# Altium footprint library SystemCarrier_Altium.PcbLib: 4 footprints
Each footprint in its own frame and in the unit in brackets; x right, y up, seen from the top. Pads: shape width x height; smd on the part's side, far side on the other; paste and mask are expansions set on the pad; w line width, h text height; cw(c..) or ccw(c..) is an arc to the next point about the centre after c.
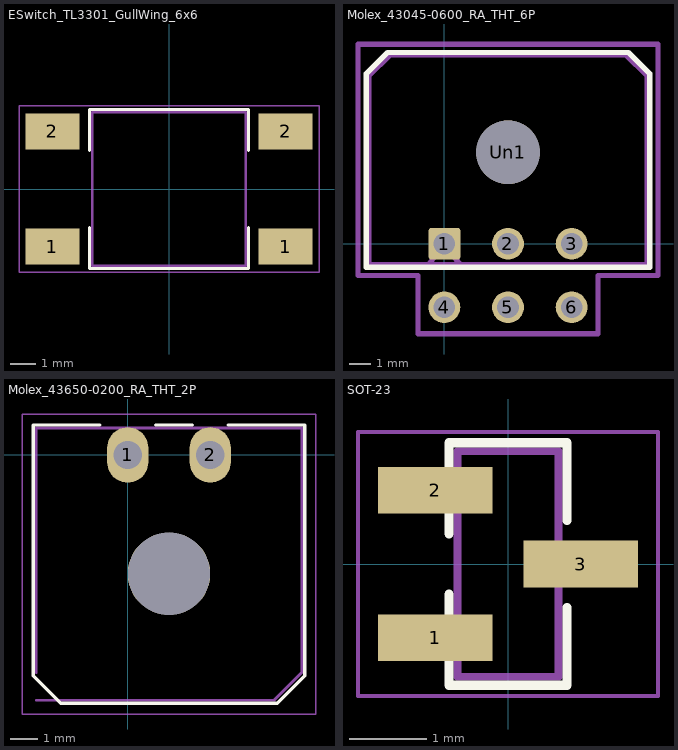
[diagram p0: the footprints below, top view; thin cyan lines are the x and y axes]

## ESwitch_TL3301_GullWing_6x6 [mm] "E-Switch TL3301 series, 6 x 6 mm gull-wing tactile switch"
height 4.3
pads (4):
  rect 2.1x1.4 smd: 1(-4.55,-2.25) 1(4.55,-2.25) 2(-4.55,2.25) 2(4.55,2.25)
F.SilkS:
  lines w0.12: -3.1,-1.5 -3.1,-3.1 3.1,-3.1 3.1,-1.5 ; -3.1,1.5 -3.1,3.1 3.1,3.1 3.1,1.5
Margin:
  lines w0.1: -3,-3 3,-3 3,3 -3,3 -3,-3
Mechanical 15:
  lines w0.05: -5.85,-3.25 5.85,-3.25 5.85,3.25 -5.85,3.25 -5.85,-3.25

## Molex_43045-0600_RA_THT_6P [mm]
pads (7):
  rrect17% 1.5x1.5 hole 1.02: 1(0,0)
  round 1.5 hole 1.02: 2(3,0) 3(6,0) 4(0,-3) 5(3,-3) 6(6,-3)
  round 3 hole 3: Un1(3,4.32)
F.SilkS:
  lines w0.254: -3.685,-1.1 9.685,-1.1 9.685,8.03 8.685,9.03 -2.685,9.03 -3.685,8.03 -3.685,-1.1
F.CrtYd:
  lines w0.254: -4.08,-1.5 -1.25,-1.5 -1.25,-4.25 7.25,-4.25 7.25,-1.5 10.08,-1.5 10.08,9.42 -4.08,9.42 -4.08,-1.5
F.Fab:
  lines w0.254: -0.75,-0.99 0,0 0.75,-0.99 ; -3.575,-0.99 9.575,-0.99 9.575,7.92 8.575,8.92 -2.575,8.92 -3.575,7.92 -3.575,-0.99
  text "'.Designator'" at -1.047,7.38 h1

## Molex_43650-0200_RA_THT_2P [mm] "Molex Micro-Fit 3.0 43650-0200, 2-position right-angle THT"
height 9.65
pads (3):
  oval 1.5x2.02 hole 1.02: 1(0,0) 2(3,0)
  round 3 hole 3 unplated: ""(1.5,-4.32)
F.SilkS:
  lines w0.12: -1.01,1.09 -3.435,1.09 -3.435,-8.03 -2.435,-9.03 5.435,-9.03 6.435,-8.03 6.435,1.09 3.65,1.09 ; 1.01,1.09 2.35,1.09
Margin:
  lines w0.1: -3.325,-8.92 5.325,-8.92 6.325,-7.92 6.325,0.98 -3.325,0.98 -3.325,-7.92
Mechanical 15:
  lines w0.05: -3.83,-9.42 6.83,-9.42 6.83,1.49 -3.83,1.49 -3.83,-9.42

## SOT-23 [mm] "JEDEC TO-236 AB, three-pad SOT-23"
height 1.2
pads (3):
  rect 1.475x0.6 smd: 1(-0.937,-0.95) 2(-0.937,0.95) 3(0.937,0)
F.SilkS:
  lines w0.12: -0.76,-0.39 -0.76,-1.56 0.76,-1.56 0.76,-0.56 ; -0.76,0.39 -0.76,1.56 0.76,1.56 0.76,0.56
Margin:
  lines w0.1: -0.65,-1.45 0.65,-1.45 0.65,1.45 -0.65,1.45 -0.65,-1.45
Mechanical 15:
  lines w0.05: -1.93,-1.7 1.93,-1.7 1.93,1.7 -1.93,1.7 -1.93,-1.7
